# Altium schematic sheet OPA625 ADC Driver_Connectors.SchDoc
size 431 x 279 mm; Date: Not shown in title block; ApprovedBy: Not shown in title block; CheckedBy: Not shown in title block; Author: Not shown in title block; CompanyName: Not shown in title block; Engineer: Not shown in title block; Organization: Not shown in title block; Address1: Not shown in title block; Address2: Not shown in title block; Address3: Not shown in title block; Address4: Not shown in title block; DocumentNumber: 3; Revision: Use project parameter SCH_Rev; SheetNumber: 3; SheetTotal: 8; PageSetup: Record=PageOptions¦CenterHorizontal=True¦CenterVertical=True¦PrintScale=0.96¦XCorrection=1.00¦YCorrection=1.00¦PrintKind=0¦BorderSize=5000000¦LeftOffset=0¦BottomOffset=0¦Orientation=2¦PaperLength=1000¦PaperWidth=1000¦Scale=100¦PaperSource=15¦PrintQuality=-3¦MediaType=1¦DitherType=10¦PrintScaleMode=1¦PaperKind=Tabloid (11 x 17")¦PaperIndex=17
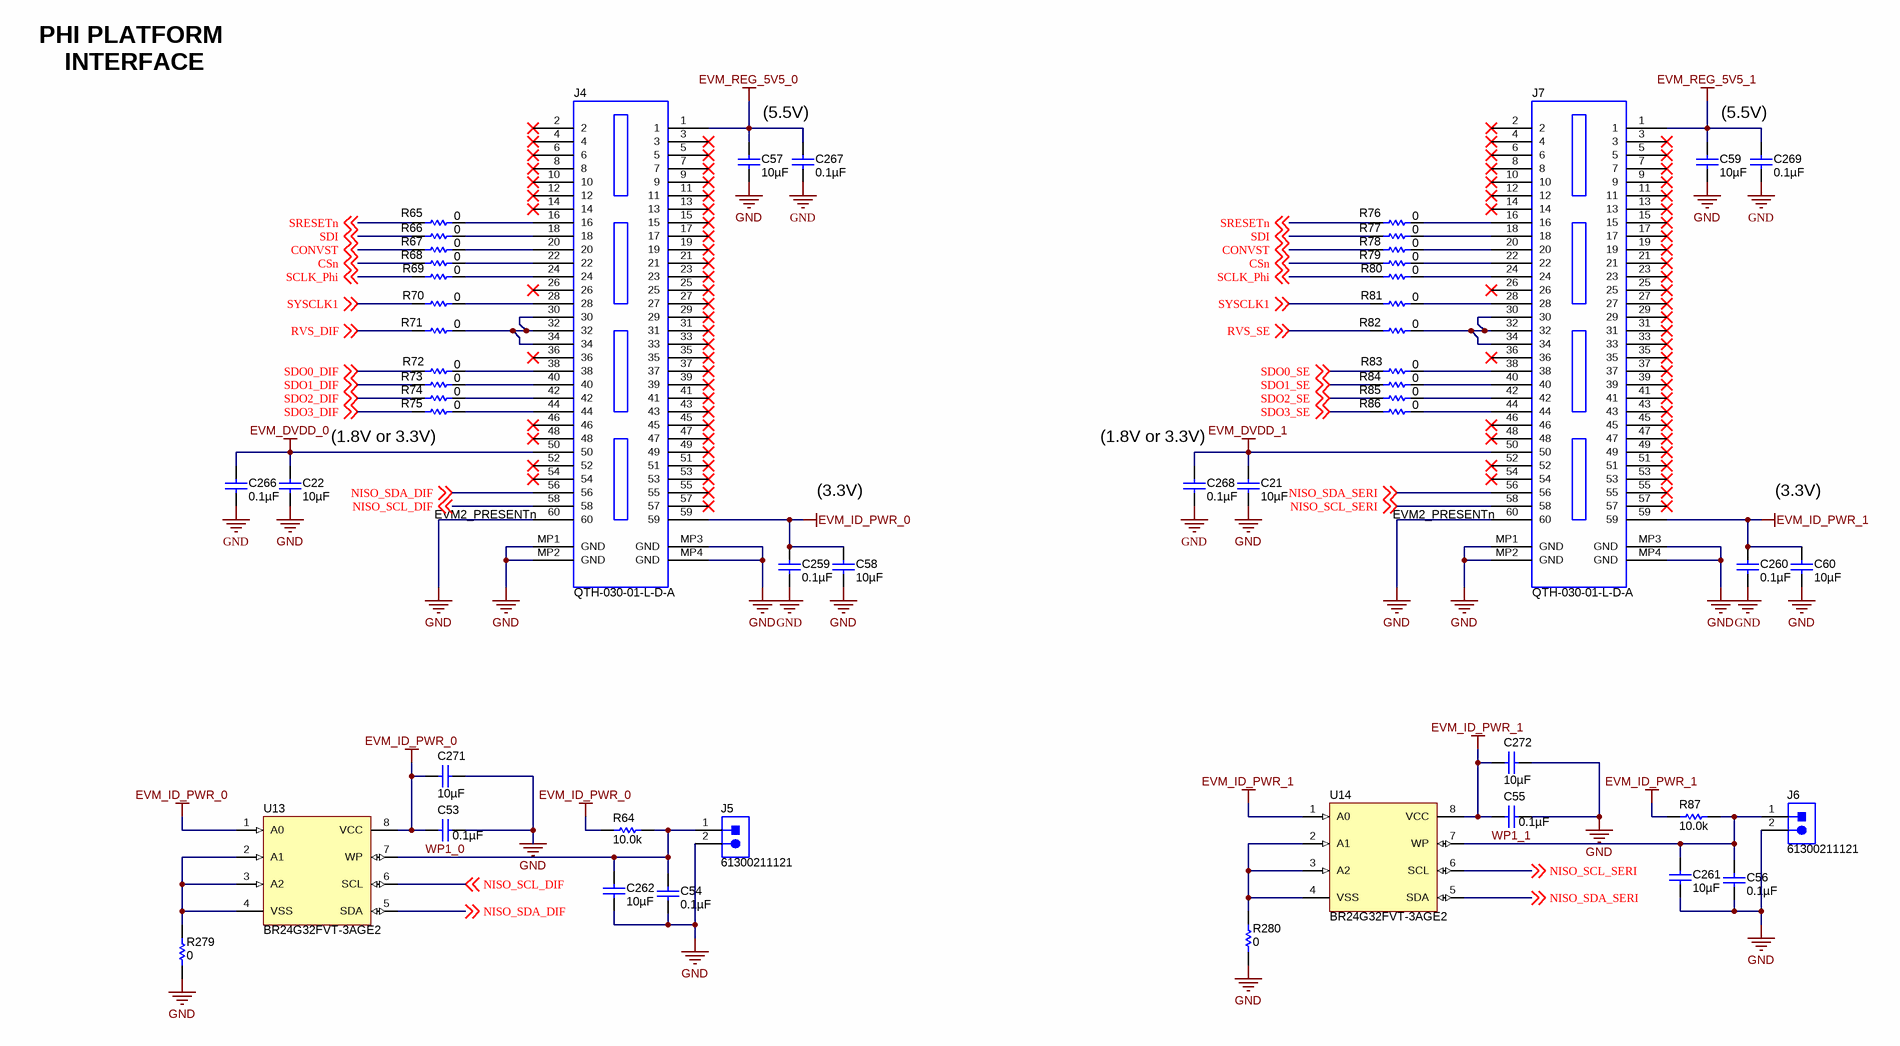
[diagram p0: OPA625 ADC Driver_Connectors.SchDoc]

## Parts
C21  ValueDisplayed: 10µF  [0805_HV]  (hidden comment: GRM21BR71A106KE51L)
C22  ValueDisplayed: 10µF  [0805_HV]  (hidden comment: GRM21BR71A106KE51L)
C53  ValueDisplayed: 0.1µF  [0402]  (hidden comment: GRM155R71C104KA88D)
C54  ValueDisplayed: 0.1µF  [0402]  (hidden comment: GRM155R71C104KA88D)
C55  ValueDisplayed: 0.1µF  [0402]  (hidden comment: GRM155R71C104KA88D)
C56  ValueDisplayed: 0.1µF  [0402]  (hidden comment: GRM155R71C104KA88D)
C57  ValueDisplayed: 10µF  [0805_HV]  (hidden comment: GRM21BR71A106KE51L)
C58  ValueDisplayed: 10µF  [0805_HV]  (hidden comment: GRM21BR71A106KE51L)
C59  ValueDisplayed: 10µF  [0805_HV]  (hidden comment: GRM21BR71A106KE51L)
C60  ValueDisplayed: 10µF  [0805_HV]  (hidden comment: GRM21BR71A106KE51L)
C259  ValueDisplayed: 0.1µF  [0603]  (hidden comment: C0603C104J3RACTU)
C260  ValueDisplayed: 0.1µF  [0603]  (hidden comment: C0603C104J3RACTU)
C261  ValueDisplayed: 10µF  [0805_HV]  (hidden comment: GRM21BR71A106KE51L)
C262  ValueDisplayed: 10µF  [0805_HV]  (hidden comment: GRM21BR71A106KE51L)
C266  ValueDisplayed: 0.1µF  [0603]  (hidden comment: C0603C104J3RACTU)
C267  ValueDisplayed: 0.1µF  [0603]  (hidden comment: C0603C104J3RACTU)
C268  ValueDisplayed: 0.1µF  [0603]  (hidden comment: C0603C104J3RACTU)
C269  ValueDisplayed: 0.1µF  [0603]  (hidden comment: C0603C104J3RACTU)
C271  ValueDisplayed: 10µF  [0805_HV]  (hidden comment: GRM21BR71A106KE51L)
C272  ValueDisplayed: 10µF  [0805_HV]  (hidden comment: GRM21BR71A106KE51L)
J4  QTH-030-01-L-D-A  [Samtec_QTH-030-01-x-D-A]
J5  61300211121  [WURTH_61300211121]
J6  61300211121  [WURTH_61300211121]
J7  QTH-030-01-L-D-A  [Samtec_QTH-030-01-x-D-A]
R64  ValueDisplayed: 10.0k  [0603]  (hidden comment: CRCW060310K0FKEA)
R65  ValueDisplayed: 0  [0402]  (hidden comment: ERJ-2GE0R00X)
R66  ValueDisplayed: 0  [0402]  (hidden comment: ERJ-2GE0R00X)
R67  ValueDisplayed: 0  [0402]  (hidden comment: ERJ-2GE0R00X)
R68  ValueDisplayed: 0  [0402]  (hidden comment: ERJ-2GE0R00X)
R69  ValueDisplayed: 0  [0402]  (hidden comment: ERJ-2GE0R00X)
R70  ValueDisplayed: 0  [0402]  (hidden comment: ERJ-2GE0R00X)
R71  ValueDisplayed: 0  [0402]  (hidden comment: ERJ-2GE0R00X)
R72  ValueDisplayed: 0  [0402]  (hidden comment: ERJ-2GE0R00X)
R73  ValueDisplayed: 0  [0402]  (hidden comment: ERJ-2GE0R00X)
R74  ValueDisplayed: 0  [0402]  (hidden comment: ERJ-2GE0R00X)
R75  ValueDisplayed: 0  [0402]  (hidden comment: ERJ-2GE0R00X)
R76  ValueDisplayed: 0  [0402]  (hidden comment: ERJ-2GE0R00X)
R77  ValueDisplayed: 0  [0402]  (hidden comment: ERJ-2GE0R00X)
R78  ValueDisplayed: 0  [0402]  (hidden comment: ERJ-2GE0R00X)
R79  ValueDisplayed: 0  [0402]  (hidden comment: ERJ-2GE0R00X)
R80  ValueDisplayed: 0  [0402]  (hidden comment: ERJ-2GE0R00X)
R81  ValueDisplayed: 0  [0402]  (hidden comment: ERJ-2GE0R00X)
R82  ValueDisplayed: 0  [0402]  (hidden comment: ERJ-2GE0R00X)
R83  ValueDisplayed: 0  [0402]  (hidden comment: ERJ-2GE0R00X)
R84  ValueDisplayed: 0  [0402]  (hidden comment: ERJ-2GE0R00X)
R85  ValueDisplayed: 0  [0402]  (hidden comment: ERJ-2GE0R00X)
R86  ValueDisplayed: 0  [0402]  (hidden comment: ERJ-2GE0R00X)
R87  ValueDisplayed: 10.0k  [0603]  (hidden comment: CRCW060310K0FKEA)
R279  ValueDisplayed: 0  [0402]  (hidden comment: ERJ-2GE0R00X)
R280  ValueDisplayed: 0  [0402]  (hidden comment: ERJ-2GE0R00X)
U13  BR24G32FVT-3AGE2  [TSOP65P640X120-8N]
U14  BR24G32FVT-3AGE2  [TSOP65P640X120-8N]

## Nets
EVM_DVDD_0: C22.1 C266.1 J4.50
EVM_DVDD_1: C21.1 C268.1 J7.50
EVM_ID_PWR_0: C53.2 C58.1 C259.1 C271.1 J4.59 R64.2 U13.1(A0) U13.8(VCC)
EVM_ID_PWR_1: C55.2 C60.1 C260.1 C272.1 J7.59 R87.2 U14.1(A0) U14.8(VCC)
EVM_REG_5V5_0: C57.1 C267.1 J4.1
EVM_REG_5V5_1: C59.1 C269.1 J7.1
GND: C21.2 C22.2 C53.1 C54.1 C55.1 C56.1 C57.2 C58.2 C59.2 C60.2 C259.2 C260.2 C261.2 C262.2 C266.2 C267.2 C268.2 C269.2 C271.2 C272.2 J4.60 J4.MP1(GND) J4.MP2(GND) J4.MP3(GND) J4.MP4(GND) J5.2 J6.2 J7.60 J7.MP1(GND) J7.MP2(GND) J7.MP3(GND) J7.MP4(GND) R279.1 R280.1
CONVST: R67.1 R78.1 ; off-sheet CONVST
CSn: R68.1 R79.1 ; off-sheet CSn
NISO_SCL_DIF: J4.58 U13.6(SCL) ; off-sheet NISO_SCL_DIF
NISO_SCL_SERI: J7.58 U14.6(SCL) ; off-sheet NISO_SCL_SERI
NISO_SDA_DIF: J4.56 U13.5(SDA) ; off-sheet NISO_SDA_DIF
NISO_SDA_SERI: J7.56 U14.5(SDA) ; off-sheet NISO_SDA_SERI
RVS_DIF: R71.1 ; off-sheet RVS_DIF
RVS_SE: R82.1 ; off-sheet RVS_SE
SCLK_Phi: R69.1 R80.1 ; off-sheet SCLK_Phi
SDI: R66.1 R77.1 ; off-sheet SDI
SDO0_DIF: R72.1 ; off-sheet SDO0_DIF
SDO0_SE: R83.1 ; off-sheet SDO0_SE
SDO1_DIF: R73.1 ; off-sheet SDO1_DIF
SDO1_SE: R84.1 ; off-sheet SDO1_SE
SDO2_DIF: R74.1 ; off-sheet SDO2_DIF
SDO2_SE: R85.1 ; off-sheet SDO2_SE
SDO3_DIF: R75.1 ; off-sheet SDO3_DIF
SDO3_SE: R86.1 ; off-sheet SDO3_SE
SRESETn: R65.1 R76.1 ; off-sheet SRESETn
SYSCLK1: R70.1 R81.1 ; off-sheet SYSCLK1
WP1_0: C54.2 C262.1 J5.1 R64.1 U13.7(WP)
WP1_1: C56.2 C261.1 J6.1 R87.1 U14.7(WP)
NetJ4_16: J4.16 R65.2
NetJ4_18: J4.18 R66.2
NetJ4_20: J4.20 R67.2
NetJ4_22: J4.22 R68.2
NetJ4_24: J4.24 R69.2
NetJ4_28: J4.28 R70.2
NetJ4_30: J4.30 J4.32 J4.34 R71.2
NetJ4_38: J4.38 R72.2
NetJ4_40: J4.40 R73.2
NetJ4_42: J4.42 R74.2
NetJ4_44: J4.44 R75.2
NetJ7_16: J7.16 R76.2
NetJ7_18: J7.18 R77.2
NetJ7_20: J7.20 R78.2
NetJ7_22: J7.22 R79.2
NetJ7_24: J7.24 R80.2
NetJ7_28: J7.28 R81.2
NetJ7_30: J7.30 J7.32 J7.34 R82.2
NetJ7_38: J7.38 R83.2
NetJ7_40: J7.40 R84.2
NetJ7_42: J7.42 R85.2
NetJ7_44: J7.44 R86.2
NetR279_2: R279.2 U13.2(A1) U13.3(A2) U13.4(VSS)
NetR280_2: R280.2 U14.2(A1) U14.3(A2) U14.4(VSS)

Not connected (* = marked no-connect by the designer): J4 2* 3* 4* 5* 6* 7* 8* 9* 10* 11* 12* 13* 14* 15* 17* 19* 21* 23* 25* 26* 27* 29* 31* 33* 35* 36* 37* 39* 41* 43* 45* 46* 47* 48* 49* 51* 52* 53* 54* 55* 57*; J7 2* 3* 4* 5* 6* 7* 8* 9* 10* 11* 12* 13* 14* 15* 17* 19* 21* 23* 25* 26* 27* 29* 31* 33* 35* 36* 37* 39* 41* 43* 45* 46* 47* 48* 49* 51* 52* 53* 54* 55* 57*

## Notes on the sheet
- PHI PLATFORM
  INTERFACE
- (5.5V)
- (near R75) (1.8V or 3.3V)
- (near C268) (1.8V or 3.3V)
- (near J4) EVM2_PRESENTn
- (3.3V)
- (near J7) EVM2_PRESENTn

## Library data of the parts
C21 C22 C57-C60 C261 C262 C271 C272 = GRM21BR71A106KE51L: CAP, CERM, 10 µF, 10 V, +/- 10%, X7R, 0805; Manufacturer: MuRata; Polarized: N; CompType: Capacitor; Value: 10uF; U/M: EA; Cap_F: 0.00001; Tolerance_%: 10; ESR_ohm: 0.003; Value1: 0.003 ohm; Value2: 10V; TaMin_C: -55; TaMax_C: 125; Cap_Case: 0805; AEC Category: Q200
C53-C56 = GRM155R71C104KA88D: CAP, CERM, 0.1 µF, 16 V, +/- 10%, X7R, 0402; Manufacturer: MuRata; Polarized: N; CompType: Capacitor; Value: 0.1uF; U/M: EA; Cap_F: 0.0000001; Tolerance_%: 10; Value1: Unknown; VDC_V: 16; Value2: 16V; TaMin_C: -55; TaMax_C: 125
C259 C260 C266-C269 = C0603C104J3RACTU: CAP, CERM, 0.1 µF, 25 V, +/- 5%, X7R, 0603; Manufacturer: Kemet; Polarized: N; CompType: Capacitor; Value: 0.1uF; U/M: EA; Cap_F: 0.0000001; Tolerance_%: 5; Value1: Unknown; VDC_V: 25; Value2: 25V; TaMin_C: -55; TaMax_C: 125
J4 J7 = QTH-030-01-L-D-A: Header(Shrouded), 19.7mil, 30x2, Gold, SMT; Manufacturer: Samtec; SymbolCreator: Altium; Pitch_mm: 0.5; Gender: Male; Shrouded: Y; Row_Count: 2
J5 J6 = 61300211121: Header, 2.54 mm, 2x1, Gold, TH; Manufacturer: Wurth Elektronik eiSos; SymbolCreator: a0412235; U/M: EA
R64 R87 = CRCW060310K0FKEA: RES, 10.0 k, 1%, 0.1 W, 0603; Manufacturer: Vishay-Dale; CompType: Resistor; Value: 10.0k; Res_ohm: 10000; Value_Code: 10k0; Tolerance_%: 1; Power_W: 0.1; Value2: 0.1W; VDC_V: 75; TempCo: 100 ppm/C; EIA_Code: E96; U/M: EA
R65-R86 R279 R280 = ERJ-2GE0R00X: RES, 0, 5%, 0.063 W, 0402; Manufacturer: Panasonic; CompType: Resistor; Value: 0; Value_Code: 0000; Tolerance_%: 5; Power_W: 0.063; Value2: 0.063W; VDC_V: 50; TempCo: 600 ppm/C; EIA_Code: E24; U/M: EA; AEC Category: Q200
U13 U14 = BR24G32FVT-3AGE2: I2C BUS EEPROM (2-Wire), TSSOP-B8; Manufacturer: Rohm; SymbolCreator: a0411947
